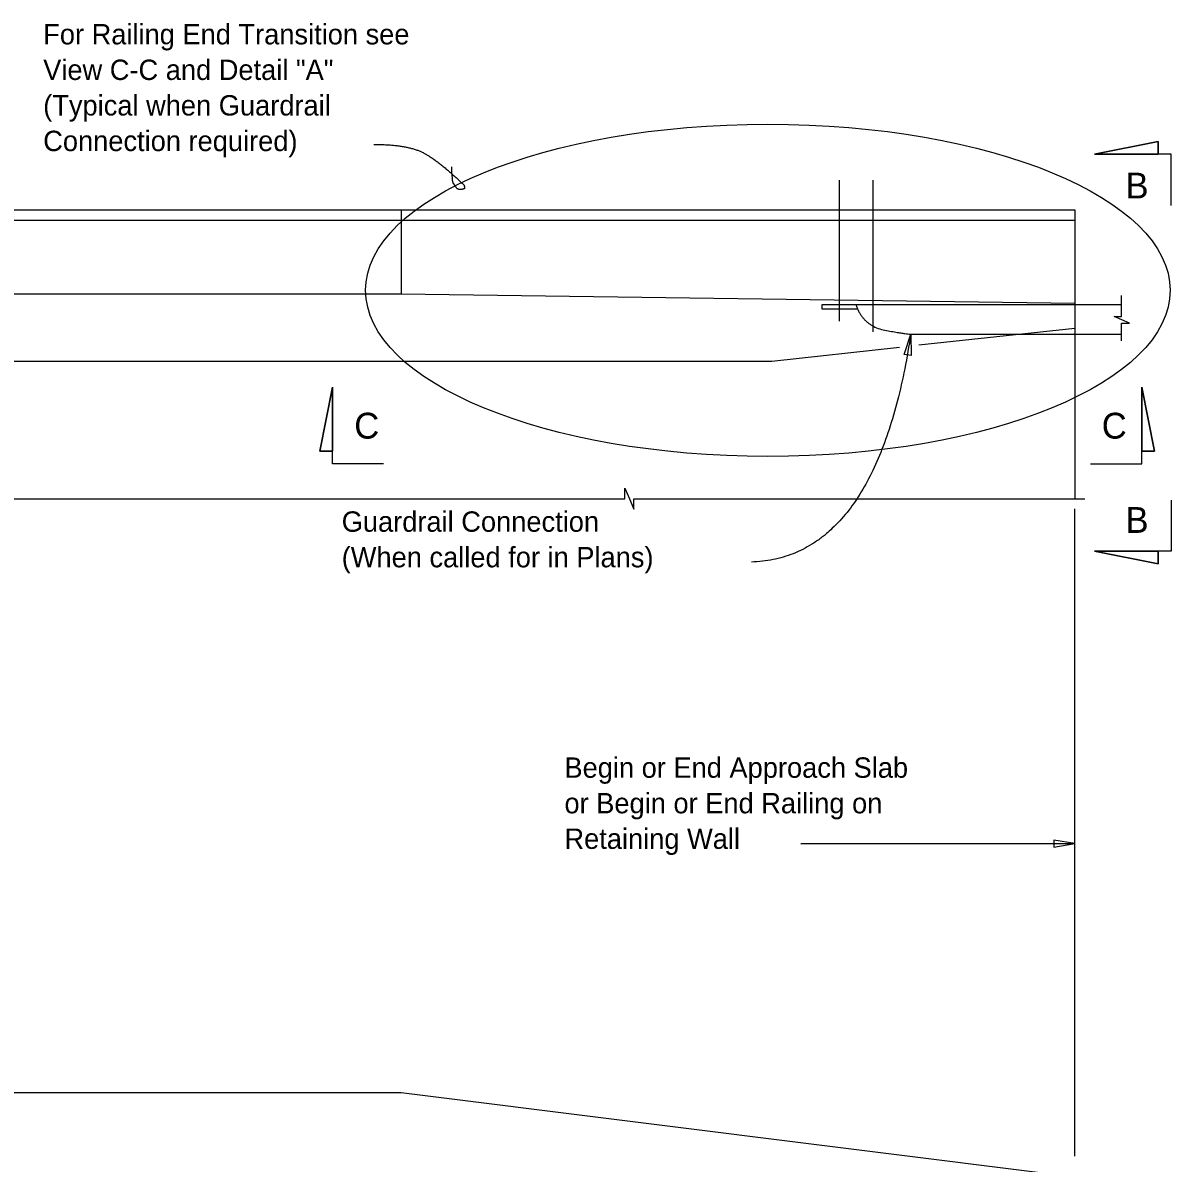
# Model space of a CAD drawing. Extents: x 0.5 to 40.8, y 1 to 25.8.
# Drawn here: x 29.41 to 40.77, y 14.49 to 25.77 of the extents above; entities that cross this region are included whole.
import ezdxf

# ---------------------------------------------------------------- set-up
doc = ezdxf.new("R2010")
doc.units = 0
for name, color, linetype in [('Dimension', 7, 'Continuous'), ('Miscellaneous', 7, 'Continuous'), ('TextStructures', 7, 'Continuous'), ('TrafBarrierConc', 7, 'Continuous')]:
    doc.layers.add(name, color=color, linetype=linetype)

msp = doc.modelspace()

# ---------------------------------------------------------------- linework, layer by layer
at = {"layer": 'Dimension'}
for p, q in [((40.012, 24.472), (40.644, 24.599)), ((40.644, 24.599), (40.644, 24.472)), ((40.771, 24.472), (40.012, 24.472)), ((40.771, 23.966), (40.771, 24.472)), ((37.484, 24.216), (37.484, 22.822)), ((37.818, 24.216), (37.818, 22.716)), ((32.47, 22.167), (32.344, 21.535)), ((32.47, 21.408), (32.47, 22.167)), ((40.482, 21.408), (40.482, 22.167)), ((40.482, 22.167), (40.608, 21.535)), ((32.344, 21.535), (32.47, 21.535)), ((40.608, 21.535), (40.482, 21.535)), ((32.976, 21.408), (32.47, 21.408)), ((39.975, 21.408), (40.482, 21.408)), ((40.771, 21.05), (40.771, 20.544)), ((39.818, 20.252), (39.818, 20.963)), ((39.818, 14.555), (39.818, 20.963)), ((40.771, 20.544), (40.012, 20.544)), ((40.012, 20.544), (40.644, 20.417)), ((40.644, 20.417), (40.644, 20.544)), ((37.107, 17.649), (39.818, 17.649))]:
    msp.add_line(p, q, dxfattribs=at)
for points in [[(40.644, 24.472), (40.644, 24.599), (40.012, 24.472)], [(38.13, 22.492), (38.195, 22.693), (38.199, 22.482)], [(32.47, 21.535), (32.344, 21.535), (32.47, 22.167)], [(40.482, 21.535), (40.608, 21.535), (40.482, 22.167)], [(40.644, 20.544), (40.644, 20.417), (40.012, 20.544)], [(39.818, 17.649), (39.61, 17.685), (39.61, 17.614)]]:
    msp.add_lwpolyline(points, close=True, dxfattribs=at)
for points in [[(33.772, 24.167), (33.772, 24.155), (33.776, 24.155), (33.776, 24.151), (33.776, 24.147), (33.776, 24.143), (33.776, 24.139), (33.776, 24.135), (33.776, 24.131), (33.772, 24.131), (33.768, 24.131), (33.768, 24.128), (33.764, 24.128), (33.76, 24.128), (33.756, 24.128), (33.756, 24.124), (33.752, 24.124), (33.749, 24.124), (33.745, 24.124), (33.741, 24.124), (33.737, 24.124), (33.733, 24.124), (33.729, 24.124), (33.725, 24.124), (33.721, 24.124), (33.717, 24.128), (33.713, 24.128), (33.709, 24.131), (33.705, 24.131), (33.701, 24.135), (33.697, 24.139), (33.697, 24.143), (33.693, 24.143), (33.693, 24.147), (33.689, 24.151), (33.689, 24.155), (33.685, 24.155), (33.685, 24.159), (33.681, 24.159), (33.681, 24.163), (33.681, 24.167), (33.677, 24.167), (33.677, 24.171), (33.673, 24.171), (33.673, 24.175), (33.67, 24.179), (33.67, 24.183), (33.666, 24.183), (33.666, 24.187), (33.666, 24.191), (33.662, 24.195), (33.662, 24.199), (33.662, 24.203), (33.662, 24.207), (33.662, 24.211), (33.658, 24.211), (33.658, 24.214), (33.658, 24.218), (33.658, 24.222), (33.658, 24.226), (33.658, 24.23), (33.658, 24.234), (33.658, 24.242), (33.654, 24.258), (33.654, 24.266), (33.654, 24.27), (33.654, 24.278), (33.65, 24.282), (33.65, 24.286), (33.65, 24.29), (33.65, 24.294), (33.65, 24.297), (33.65, 24.301), (33.65, 24.305), (33.65, 24.309), (33.65, 24.317), (33.65, 24.325), (33.65, 24.329), (33.65, 24.337), (33.65, 24.341), (33.65, 24.345), (33.65, 24.349), (33.65, 24.349)], [(40.281, 22.627), (40.281, 22.802), (40.359, 22.802), (40.209, 22.868), (40.281, 22.868), (40.281, 23.075)], [(23.737, 21.063), (24.629, 21.063), (24.629, 21.167), (24.674, 21.063), (24.719, 20.96), (24.719, 21.063), (30.61, 21.063)], [(30.61, 21.063), (35.364, 21.063), (35.364, 21.167), (35.409, 21.063), (35.454, 20.96), (35.454, 21.063), (39.919, 21.063)]]:
    msp.add_lwpolyline(points, dxfattribs=at)
msp.add_ellipse((36.78, 23.126), major_axis=(-3.982, 0), ratio=0.412977, dxfattribs=at)
for points in [[(32.88, 24.57), (33.211, 24.57), (33.527, 24.404), (33.772, 24.167)], [(38.195, 22.693), (37.858, 20.475), (36.617, 20.436)]]:
    msp.add_open_spline(points, degree=2, dxfattribs=at)
at = {"layer": 'Miscellaneous'}
for p, q in [((37.318, 22.984), (40.281, 22.984)), ((37.318, 22.938), (37.318, 22.984)), ((37.66, 22.938), (37.318, 22.938)), ((38.195, 22.693), (40.281, 22.693))]:
    msp.add_line(p, q, dxfattribs=at)
msp.add_open_spline([(37.651, 22.984), (37.721, 22.772), (38.161, 22.69), (38.195, 22.693)], degree=2, dxfattribs=at)
at = {"layer": 'TrafBarrierConc'}
for p, q in [((23.837, 23.924), (39.818, 23.924)), ((33.151, 23.924), (33.151, 23.091)), ((39.818, 23.924), (39.818, 21.063)), ((23.837, 23.82), (33.151, 23.82)), ((33.151, 23.82), (39.818, 23.82)), ((23.837, 23.091), (33.151, 23.091)), ((33.151, 23.091), (39.818, 23)), ((38.273, 22.586), (39.818, 22.75)), ((36.818, 22.424), (38.082, 22.564)), ((23.837, 22.424), (36.818, 22.424)), ((23.987, 15.185), (33.151, 15.185)), ((33.151, 15.185), (39.818, 14.351))]:
    msp.add_line(p, q, dxfattribs=at)

# ---------------------------------------------------------------- texts
at = {"layer": 'Dimension'}
for s, p in [('For Railing End Transition see ', (29.606, 25.56)), ('View C-C and Detail "A" ', (29.606, 25.208)), ('(Typical when Guardrail', (29.606, 24.856)), ('Connection required)', (29.606, 24.504)), ('Guardrail Connection', (32.561, 20.736)), ('(When called for in Plans)', (32.561, 20.384)), ('Begin or End Approach Slab ', (34.766, 18.301)), ('or Begin or End Railing on ', (34.766, 17.949)), ('Retaining Wall', (34.766, 17.597))]:
    msp.add_text(s, height=0.2016, dxfattribs=at).set_placement(p)
at = {"layer": 'TextStructures'}
for s, p in [('B', (40.32, 24.035)), ('C', (32.685, 21.658)), ('C', (40.085, 21.658)), ('B', (40.32, 20.725))]:
    msp.add_text(s, height=0.256, dxfattribs=at).set_placement(p)

doc.saveas('drawing.dxf')
